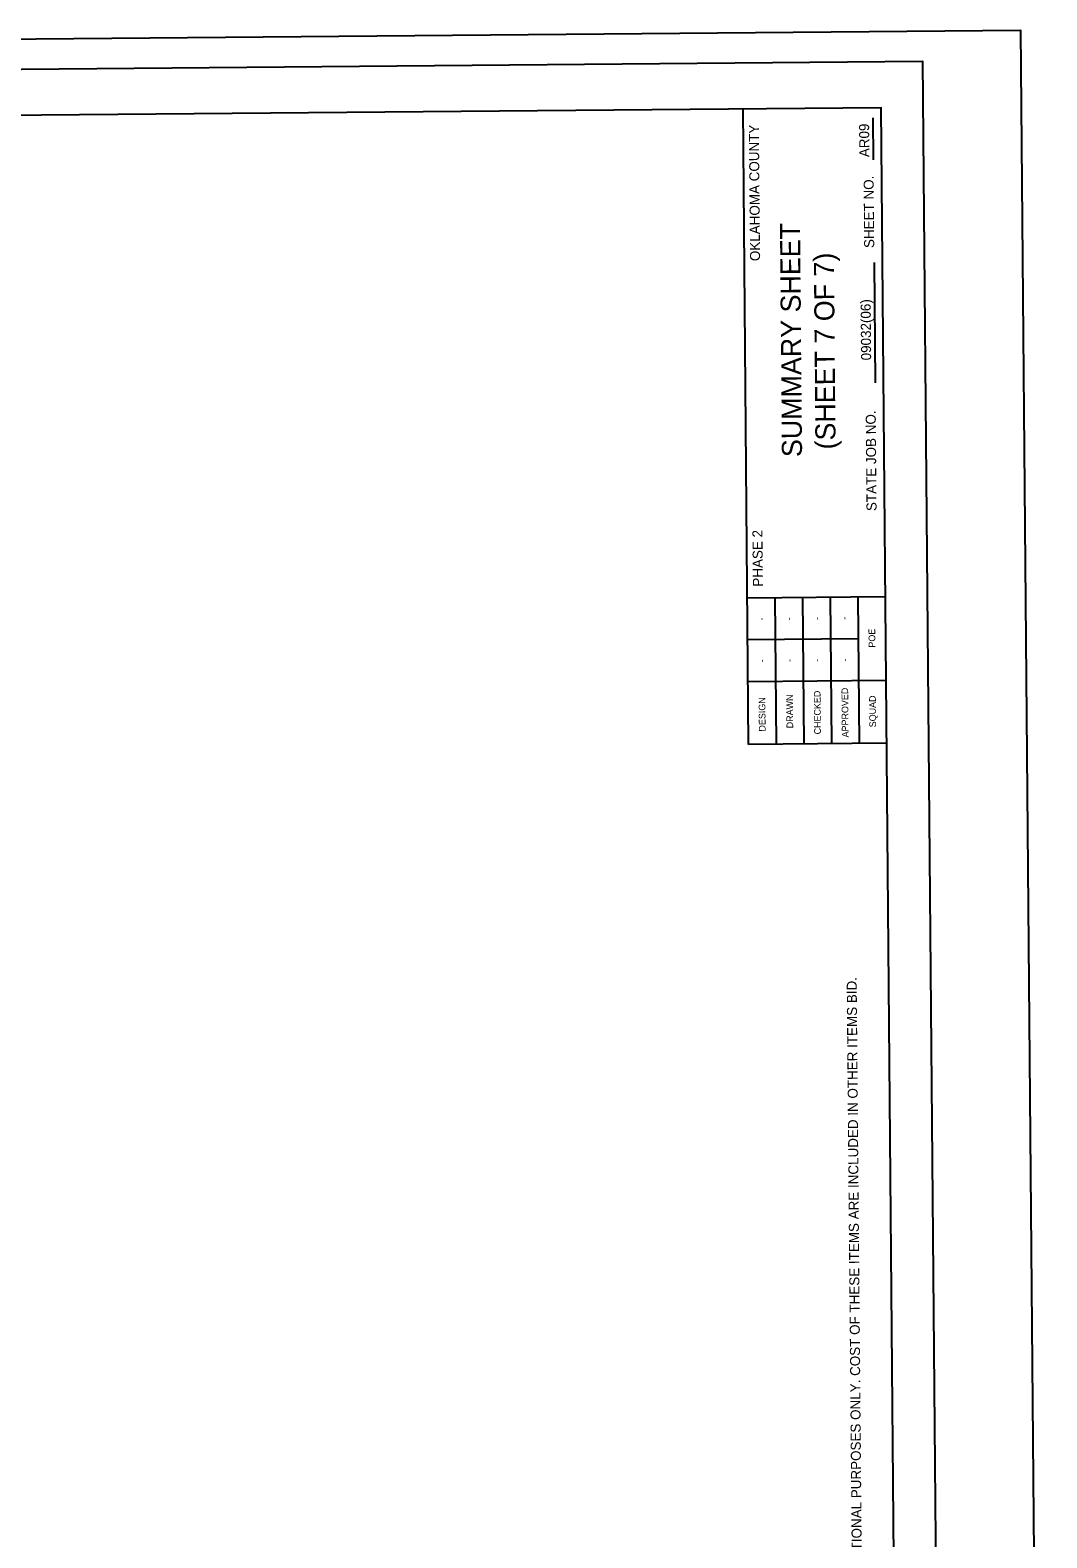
# Model space of a CAD drawing. Extents: x 2151900 to 2151925, y 142567 to 142723.
# Drawn here: x 2151911.88 to 2151924.04, y 142705.37 to 142723.4 of the extents above; entities that cross this region are included whole.
import ezdxf

# ---------------------------------------------------------------- set-up
doc = ezdxf.new("R2010")
doc.units = 0
for name, color, linetype in [('SHT_Plot_Shape_Full', 7, 'Continuous'), ('SHT_Plot_Shape_Half', 7, 'Continuous'), ('SHT_Sheet_Border', 7, 'Continuous'), ('SHT_Standard_Sheet_Lines', 7, 'Continuous'), ('SHT_Standard_Sheet_Txt', 7, 'Continuous'), ('TYP_Typical_Section_Txt', 7, 'Continuous')]:
    doc.layers.add(name, color=color, linetype=linetype)

msp = doc.modelspace()

# ---------------------------------------------------------------- linework, layer by layer
at = {"layer": 'SHT_Plot_Shape_Full'}
msp.add_lwpolyline([(2151900.042, 142687.196), (2151899.727, 142723.194), (2151923.726, 142723.404), (2151924.041, 142687.406)], close=True, dxfattribs=at)
at = {"layer": 'SHT_Plot_Shape_Half'}
msp.add_lwpolyline([(2151900.853, 142688.84), (2151900.555, 142722.839), (2151922.554, 142723.032), (2151922.852, 142689.033)], close=True, dxfattribs=at)
at = {"layer": 'SHT_Sheet_Border'}
for p, q in [((2151920.475, 142714.863), (2151920.409, 142722.463)), ((2151922.11, 142716.627), (2151920.459, 142716.613)), ((2151922.125, 142714.877), (2151920.475, 142714.863))]:
    msp.add_line(p, q, dxfattribs=at)
msp.add_lwpolyline([(2151922.335, 142690.978), (2151922.059, 142722.477), (2151901.06, 142722.293), (2151901.335, 142690.795)], close=True, dxfattribs=at)
at = {"layer": 'SHT_Standard_Sheet_Lines'}
for p, q in [((2151921.968, 142721.852), (2151921.964, 142722.354)), ((2151921.992, 142719.187), (2151921.979, 142720.627)), ((2151921.784, 142716.124), (2151920.464, 142716.113)), ((2151922.119, 142715.627), (2151920.468, 142715.613))]:
    msp.add_line(p, q, dxfattribs=at)
for points in [[(2151920.79, 142716.616), (2151920.805, 142714.866)], [(2151921.12, 142716.619), (2151921.135, 142714.869)], [(2151921.45, 142716.622), (2151921.465, 142714.872)], [(2151921.78, 142716.624), (2151921.795, 142714.875)]]:
    msp.add_lwpolyline(points, dxfattribs=at)

# ---------------------------------------------------------------- texts
at = {"layer": 'SHT_Standard_Sheet_Txt'}
for s, height, p in [('OKLAHOMA COUNTY', 0.12, (2151920.612, 142720.643)), ('AR09', 0.12, (2151921.919, 142721.886)), ('SHEET NO. ', 0.12, (2151921.977, 142720.8)), ('SUMMARY SHEET', 0.24, (2151921.114, 142718.3)), ('(SHEET 7 OF 7)', 0.24, (2151921.515, 142718.391)), ('09032(06)', 0.12, (2151921.94, 142719.456)), ('STATE JOB NO.', 0.12, (2151922.005, 142717.654)), ('PHASE 2', 0.12, (2151920.646, 142716.75)), ('-', 0.08, (2151920.667, 142716.345)), ('-', 0.08, (2151920.997, 142716.348)), ('-', 0.08, (2151921.327, 142716.351)), ('-', 0.08, (2151921.657, 142716.354)), ('POE', 0.08, (2151921.99, 142716.021)), ('-', 0.08, (2151920.671, 142715.845)), ('-', 0.08, (2151921.001, 142715.848)), ('-', 0.08, (2151921.331, 142715.851)), ('-', 0.08, (2151921.662, 142715.854)), ('DESIGN', 0.08, (2151920.678, 142715.017)), ('DRAWN', 0.08, (2151921.008, 142715.056)), ('CHECKED', 0.08, (2151921.339, 142714.983)), ('APPROVED', 0.08, (2151921.67, 142714.947)), ('SQUAD', 0.08, (2151921.999, 142715.068))]:
    msp.add_text(s, height=height, rotation=90.5015, dxfattribs=at).set_placement(p)
at = {"layer": 'TYP_Typical_Section_Txt'}
msp.add_text('(1) QUANTITIES SHOWN ARE FOR INFORMATIONAL PURPOSES ONLY. COST OF THESE ITEMS ARE INCLUDED IN OTHER ITEMS BID.', height=0.12, rotation=90.5015, dxfattribs=at).set_placement((2151921.857, 142701.82))

doc.saveas('drawing.dxf')
